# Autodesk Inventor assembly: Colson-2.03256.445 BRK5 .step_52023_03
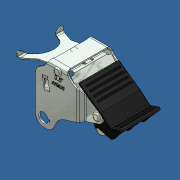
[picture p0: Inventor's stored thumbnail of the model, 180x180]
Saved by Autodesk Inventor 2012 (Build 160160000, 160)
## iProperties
Created: 2010-10
Part Number: Colson-2.03256.445 BRK5 .step_52023_03
Document SubType Name: Assembly
Designer: Administrator
Mass: 147.752 g
Surface Area: 331.08 cm^2
Volume: 35.2296 cm^3
Density: 4.19398 g/cm^3
Author: Administrator
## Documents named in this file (5)
- C:\Andys Backup Data\ANDY'S INVENTOR\INVENTOR LIBRARIES\PARTS LIBRARY\FEET WHEELS FLOOR FASTENING SUPPORTS\SUBCOMPONENTS\21.9401 BRK_ASSY.iam
- C:\Andys Backup Data\ANDY'S INVENTOR\INVENTOR LIBRARIES\PARTS LIBRARY\FEET WHEELS FLOOR FASTENING SUPPORTS\SUBCOMPONENTS\21.9401 BRAKE.ipt
- C:\Andys Backup Data\ANDY'S INVENTOR\INVENTOR LIBRARIES\PARTS LIBRARY\FEET WHEELS FLOOR FASTENING SUPPORTS\SUBCOMPONENTS\21.9401 TOTAL LK FORK.ipt
- C:\Andys Backup Data\ANDY'S INVENTOR\INVENTOR LIBRARIES\PARTS LIBRARY\FEET WHEELS FLOOR FASTENING SUPPORTS\SUBCOMPONENTS\21.9401 CROSS BOLT.ipt
- C:\Andys Backup Data\ANDY'S INVENTOR\INVENTOR LIBRARIES\PARTS LIBRARY\FEET WHEELS FLOOR FASTENING SUPPORTS\SUBCOMPONENTS\21.9401 BRK FORK.ipt
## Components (5 placed, 4 different names)
1. Colson-2.03256.445 BRK5 .step_52023_10:1
2. Colson-2.03256.445 BRK5 .step_52023_13:1
3. Colson-2.03256.445 BRK5 .step_52023_02:1
4. Colson-2.03256.445 BRK5 .step_52023_19:1 — Insert:1
5. Colson-2.03256.445 BRK5 .step_52023_02:2 — Insert:1
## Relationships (1: Insert 1)
- Insert:1: Colson-2.03256.445 BRK5 .step_52023_19:1 ↔ Colson-2.03256.445 BRK5 .step_52023_02:2
